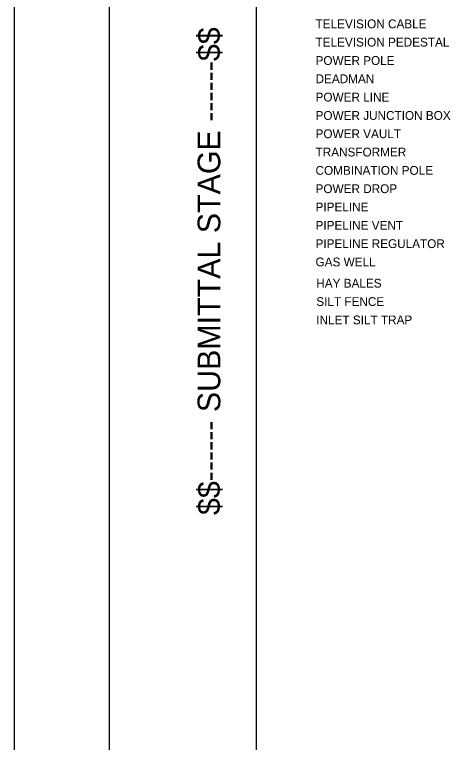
# Model space of a CAD drawing. Extents: x -1.93 to 2.83, y -1.79 to 1.85.
# Drawn here: x 0 to 0.352, y 0.559 to 1.136 of the extents above; entities that cross this region are included whole.
import ezdxf

# ---------------------------------------------------------------- set-up
doc = ezdxf.new("R2010")
doc.units = 0
for name, color, linetype in [('Legend', 7, 'Continuous'), ('Plot Border', 7, 'Continuous'), ('Plot Border 2', 7, 'Continuous'), ('Sheet Border', 7, 'Continuous')]:
    doc.layers.add(name, color=color, linetype=linetype)

msp = doc.modelspace()

# ---------------------------------------------------------------- linework, layer by layer
at = {"layer": 'Plot Border'}
for points in [[(0, 1.83333), (2.83333, 1.83333), (2.83333, 0), (0, 0)], [(2.825, 1.79583), (0.075, 1.79583), (0.075, 0.0375), (2.825, 0.0375)]]:
    msp.add_lwpolyline(points, close=True, dxfattribs=at)
at = {"layer": 'Plot Border 2'}
msp.add_lwpolyline([(0, 1.8125), (2.83333, 1.8125), (2.83333, 0.02083), (0, 0.02083)], close=True, dxfattribs=at)
at = {"layer": 'Sheet Border'}
msp.add_line((0.19167, 1.79167), (0.19167, 0.04167), dxfattribs=at)

# ---------------------------------------------------------------- texts
at = {"layer": 'Legend'}
for s, height, p in [('TELEVISION CABLE', 0.0069667, (0.23871, 1.12499)), ('TELEVISION PEDESTAL', 0.0069667, (0.23871, 1.11049)), ('POWER POLE', 0.006967, (0.23871, 1.09595)), ('DEADMAN', 0.006967, (0.23871, 1.08145)), ('POWER LINE', 0.006967, (0.23871, 1.06695)), ('POWER JUNCTION BOX', 0.0069667, (0.23871, 1.05241)), ('POWER VAULT', 0.0069667, (0.23871, 1.03791)), ('TRANSFORMER', 0.0069667, (0.23871, 1.02341)), ('COMBINATION POLE', 0.0069667, (0.23871, 1.00887)), ('POWER DROP', 0.006967, (0.23871, 0.99437)), ('PIPELINE', 0.006967, (0.23871, 0.97987)), ('PIPELINE VENT', 0.0069667, (0.23871, 0.96533)), ('PIPELINE REGULATOR', 0.0069667, (0.23871, 0.95083)), ('GAS WELL', 0.006967, (0.23871, 0.93633)), ('HAY BALES', 0.006967, (0.2393, 0.91948)), ('SILT FENCE', 0.006967, (0.2393, 0.90493)), ('INLET SILT TRAP', 0.0069667, (0.2393, 0.89039))]:
    msp.add_text(s, height=height, dxfattribs=at).set_placement(p)
at = {"layer": 'Plot Border'}
msp.add_text('$$------ SUBMITTAL STAGE ------$$', height=0.018, rotation=90, dxfattribs=at).set_placement((0.16317, 0.73926))

doc.saveas('drawing.dxf')
